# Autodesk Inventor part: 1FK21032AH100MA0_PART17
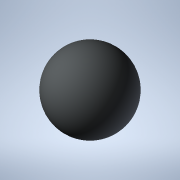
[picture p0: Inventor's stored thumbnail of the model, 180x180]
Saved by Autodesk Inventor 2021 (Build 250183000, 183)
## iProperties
Created: 2025-04
Part Number: 1FK21032AH100MA0_PART17
Material: Generic
Catalog Web Link: www.3dfindit.com
Description: -Servo synchronous motor
Document SubType Name: Modeling
Designer: psAdmin
Mass: 0.113097 g
Surface Area: 1.13097 cm^2
Volume: 0.113097 cm^3
Density: 1 g/cm^3
Appearance: PSOLRGB-212-217-219
Category: PARTsolutions
Title: 1FK21032AH100MA0_PART17
Author: Cadenas PARTsolutions
Comments: Servo synchronous motor
Sending System: PARTsolutions
Preprocessor: ST-DEVELOPER v19.3
PSOL_IDENT_0: {$CADENAS_DATA/23d-libs/siemens_ag/_cat_/12/33/1fk21032ah100ma0.prj},216 {VTYP=3D},{NB=1FK21032AH100
PSOL_IDENT_1: MA0_PART17},{LINA=1FK21032AH100MA0_PART17},{NN=1FK21032AH100MA0_PART17},{NOPRJ=TRUE},{DATE=19.08.202
PSOL_IDENT_2: 5 14:00:27},{GEOMDATE=30.07.2025 02:02:58},{VERSION=},{LINEID=10},{WBVAR=},{WBNUMERIC=}  {NB=1FK2103
PSOL_IDENT_3: 2AH100MA0_PART17},{LINA=1FK21032AH100MA0_PART17},{KT=DUMMY},{PREVIEW=../../../_pool_/d3/78/p_d211_xx
PSOL_IDENT_4: _00934j.png},{DESCSHORT=SIMOTICS S-1FK2 HD, SINAMICS S210 3AC 400V-480V, 0.59 Nm, 4500 rpm},{DESCLON
PSOL_IDENT_5: G=SIMOTICS S-1FK2 HD servo motor M0=0.64 Nm; PN = 0.28 kW at nN=4500 rpm (380-480 V); PN = 0.167 kW
PSOL_IDENT_6: at nN=2500 rpm (200-240 V); with holding brake; degree of protection IP64; cylindrical shaft D14 x 3
PSOL_IDENT_7: 0 mm; absolute encoder 22-bit + 12-bit multiturn (encoder AM22DQC); with OCC interface; plug size M1
PSOL_IDENT_8: 7, rotatable; SIMOTICS S-1FK2 servomotorfor a wide range of uses in industrial environments. SIMOTIC
PSOL_IDENT_9: S S‑1FK2 servomotors are compact synchronous motors with a high dynamic performance that set themsel
PSOL_IDENT_10: ves apart as a result of their high power density, degree of protection and overload capability. The
PSOL_IDENT_11: motors are available in two variants: as High Dynamic variant (highest dynamic performance as a res
PSOL_IDENT_12: ult of the low intrinsic moment of inertia for applications demanding a high dynamic performance wit
PSOL_IDENT_13: h low moved masses) - and as Compact variant (precise and stable closed-loop control for medium up t
PSOL_IDENT_14: o large moved masses as a result of a medium intrinsic moment of inertia). SIMOTICSS‑1FK2 servomotor
PSOL_IDENT_15: s fully exploit their strengths in a system with the SINAMICSS210 frequency converter and simple con
PSOL_IDENT_16: nection using the one cable connection (OCC). Advantages include the short control and positioning t
PSOL_IDENT_17: imes, fast and precise correction of disturbing quantities as well as stable control with a high dyn
PSOL_IDENT_18: amic performance. The servo motors can be configured to address a wide range of requirements. For ex
PSOL_IDENT_19: ample with and without holding brake, IP64 or IP65 degree of protection, singleturn or multiturn abs
PSOL_IDENT_20: olute encoders - to name just a few. Further, the servomotors are available in different shaft heigh
PSOL_IDENT_21: ts extending from 20 to 100. A shaft sealing ring is available to achieve an IP65 degree of protecti
PSOL_IDENT_22: on and for subsequent mounting at the motor or as spare part. SIMOTICS - the optimum motor for each
PSOL_IDENT_23: and every motion control application.},{INTNO=195125315563},{SUPPLIERALTNO=1FK2103-2AH10-0MA0},{MANU
PSOL_IDENT_24: ID=1FK21032AH100MA0},{MANUNAME=Siemens},{MANUTYPEDESC=SYNCHRONOUS MOTOR 1FK2 HD 0,64 NM},{AAU732=SIM
PSOL_IDENT_25: OTICS},{AAO057=S-1FK2},{AAU734=SIMOTICS S-1FK2 HD servo motor M0=0.64 Nm; PN = 0.28 kW at nN=4500 rp
PSOL_IDENT_26: m (380-480 V); PN = 0.167 kW at nN=2500 rpm (200-240 V); with holding brake; degree of protection IP
PSOL_IDENT_27: 64; cylindrical shaft D14 x 30 mm; absolute encoder 22-bit + 12-bit multiturn (encoder AM22DQC); wit
PSOL_IDENT_28: h OCC interface; plug size M17, rotatable;},{AAW338=SYNCHRONOUS MOTOR 1FK2 HD 0,64 NM},{AAO742=SIMOT
PSOL_IDENT_29: ICS},{AAO663=4034106444723},{NOCUPEROU=1},{PRICEQUANTITY=1},{QUANTITYMIN=1},{QUANTITYINT=1},{CTN=850
PSOL_IDENT_30: 15100},{COO=RO},{AAO676=1FK2103-2AH10-0MA0},{AAO677=Siemens AG},{ORDERUNIT=C62},{CONTENTUNIT=C62}
NB: 1FK21032AH100MA0_PART17
NT: Servo synchronous motor
NBSYN: $MANUID._PART17
LINA: 1FK21032AH100MA0_PART17
CATALOG: SIEMENS
PREVIEW: ../../../_pool_/d3/78/p_d211_xx_00934j.png
DESCSHORT: SIMOTICS S-1FK2 HD, SINAMICS S210 3AC 400V-480V, 0.59 Nm, 4500 rpm
DESCLONG: SIMOTICS S-1FK2 HD servo motor M0=0.64 Nm; PN = 0.28 kW at nN=4500 rpm (380-480 V); PN = 0.167 kW at nN=2500 rpm (200-240 V); with holding brake; degree of prot
INTNO: 195125315563
SUPPLIERALTNO: 1FK2103-2AH10-0MA0
MANUID: 1FK21032AH100MA0
MANUNAME: Siemens
MANUTYPEDESC: SYNCHRONOUS MOTOR 1FK2 HD 0,64 NM
AAU732: SIMOTICS
AAO057: S-1FK2
AAU734: SIMOTICS S-1FK2 HD servo motor M0=0.64 Nm; PN = 0.28 kW at nN=4500 rpm (380-480 V); PN = 0.167 kW at nN=2500 rpm (200-240 V); with holding brake; degree of prot
AAW338: SYNCHRONOUS MOTOR 1FK2 HD 0,64 NM
AAO742: SIMOTICS
AAO663: 4034106444723.0
NOCUPEROU: 1
PRICEQUANTITY: 1
QUANTITYMIN: 1
QUANTITYINT: 1
CTN: 85015100
COO: RO
ARTICLENO: 1FK21032AH100MA0_PART17
BOMINFO: 1FK21032AH100MA0_PART17
CREATOR: CADENAS GmbH
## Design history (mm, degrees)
feature "2025_04_17_15_06_16_0705"
body "Solid1"
